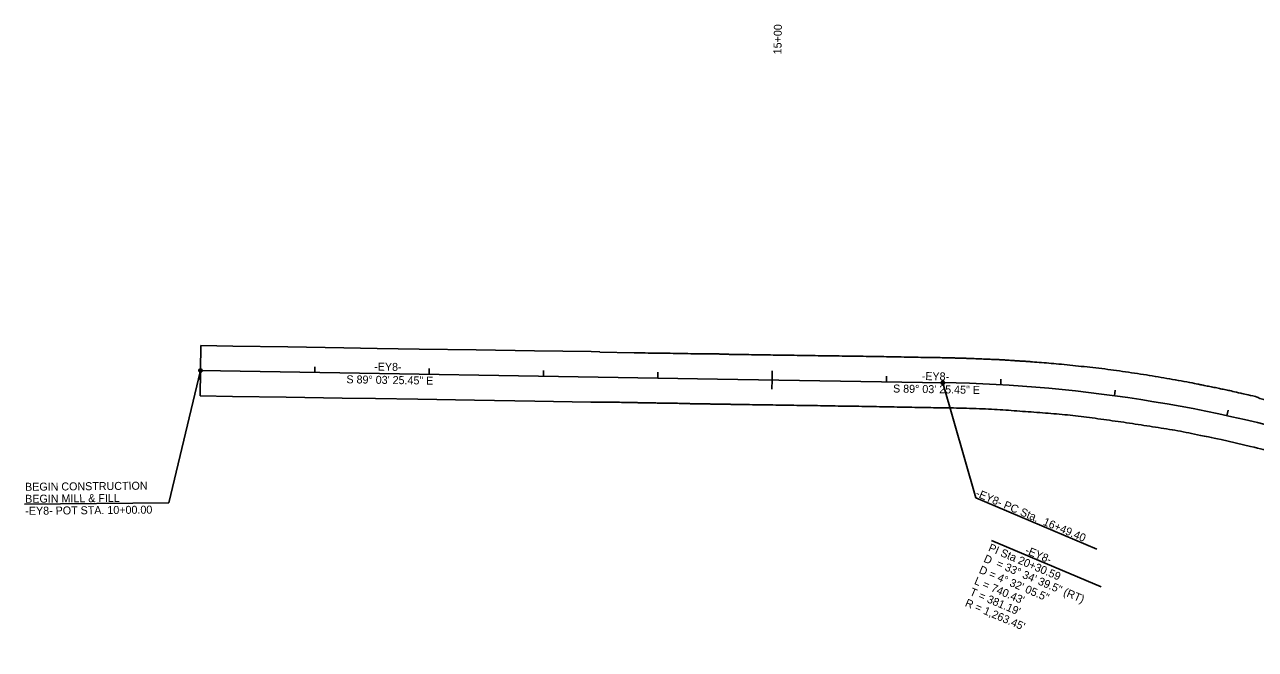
# Model space of a CAD drawing. Extents: x 1616561 to 1622460, y 896726 to 899651.
# Drawn here: x 1616561 to 1617638, y 899105 to 899651 of the extents above; entities that cross this region are included whole.
import ezdxf

# ---------------------------------------------------------------- set-up
doc = ezdxf.new("R2010")
doc.units = 0
for name, color, linetype in [('Prop Dimension Text', 7, 'Continuous'), ('Prop DSN Text', 7, 'Continuous'), ('Prop EOT', 7, 'Continuous'), ('Prop Horizontal Alignment Tick Label', 7, 'Continuous'), ('Prop Shade Light', 7, 'Continuous'), ('Prop Shade Medium', 7, 'Continuous'), ('Prop Terminator CELL', 7, 'Continuous'), ('Sheet North Arrow CELL', 7, 'Continuous'), ('Sheet Title CELL', 7, 'Continuous')]:
    doc.layers.add(name, color=color, linetype=linetype)

msp = doc.modelspace()

# ---------------------------------------------------------------- linework, layer by layer
at = {"layer": 'Prop DSN Text'}
for p, q in [((1617364.6, 899338.1), (1617393.5, 899237.4)), ((1617393.5, 899237.4), (1617499.3, 899192.6))]:
    msp.add_line(p, q, dxfattribs=at)
for centre in [(1616715.3, 899348.7), (1617364.6, 899338.1)]:
    msp.add_circle(centre, 1.5, dxfattribs=at)
at = {"layer": 'Prop Horizontal Alignment Tick Label'}
for p, q in [((1616715.3, 899348.7), (1616715.4, 899356.7)), ((1616715.3, 899348.7), (1616715.1, 899340.7)), ((1617215.2, 899340.5), (1617215.3, 899348.5)), ((1617215.2, 899340.5), (1617215.1, 899332.5))]:
    msp.add_line(p, q, dxfattribs=at)
at = {"layer": 'Prop Shade Light'}
for p, q in [((1616715.6, 899370.5), (1616715.3, 899348.7)), ((1616869.9, 899368.1), (1616840.6, 899368.6)), ((1617064.5, 899364.9), (1617064.6, 899365.2)), ((1617094.5, 899364.2), (1617064.5, 899364.9)), ((1616715.3, 899348.7), (1616714.9, 899326.6)), ((1616715.3, 899348.7), (1617167.6, 899341.3)), ((1617167.6, 899341.3), (1616715.3, 899348.7)), ((1616815.3, 899347.1), (1616815.3, 899352.1)), ((1616915.3, 899345.5), (1616915.3, 899350.5)), ((1617015.2, 899343.8), (1617015.3, 899348.8)), ((1617115.2, 899342.2), (1617115.3, 899347.2)), ((1617315.2, 899338.9), (1617315.3, 899343.9)), ((1617167.6, 899341.3), (1617364.6, 899338.1)), ((1617364.6, 899338.1), (1617167.6, 899341.3)), ((1617415.2, 899336.2), (1617415.4, 899341.2)), ((1617514.7, 899326.6), (1617515.3, 899331.6)), ((1617613.1, 899309.2), (1617614.2, 899314.1)), ((1617608.1, 899288.4), (1617633.7, 899282.4))]:
    msp.add_line(p, q, dxfattribs=at)
for points in [[(1616840.6, 899368.6), (1616791.7, 899369.4), (1616743.5, 899370.1), (1616715.6, 899370.5)], [(1617064.6, 899365.2), (1617057.1, 899365.3), (1617007.4, 899365.9), (1616956.5, 899366.8), (1616906.6, 899367.5), (1616869.9, 899368.1)], [(1616714.9, 899326.6), (1616743.4, 899326.1), (1616790.3, 899325.4), (1616839.1, 899324.6), (1616868.5, 899324.2)], [(1616868.5, 899324.2), (1616905.3, 899323.6), (1616955, 899322.8), (1617007.6, 899322), (1617056.8, 899321.1), (1617064.1, 899321), (1617064.3, 899321.2)]]:
    msp.add_lwpolyline(points, dxfattribs=at)
msp.add_arc((1617343.8, 898074.8), 1263.5, 55.4794, 89.0571, dxfattribs=at)
msp.add_arc((1617343.8, 898074.8), 1263.5, 55.4794, 89.0571, dxfattribs=at)
for points in [[(1617638, 899325.9), (1617631.3, 899327.5), (1617624.6, 899329), (1617617.9, 899330.6), (1617613.3, 899331.7), (1617608.7, 899332.5), (1617604.2, 899333.5), (1617599.3, 899334.5), (1617594.5, 899335.4), (1617589.7, 899336.4), (1617589, 899336.6), (1617588.4, 899336.7), (1617587.8, 899336.8), (1617577.9, 899338.9), (1617568, 899340.5), (1617558.1, 899342.2), (1617547.8, 899344), (1617537.4, 899345.7), (1617527, 899347.2), (1617516.6, 899348.8), (1617506.2, 899350.1), (1617495.7, 899351.3), (1617485.7, 899352.4), (1617475.7, 899353.5), (1617465.7, 899354.4), (1617457.3, 899355.2), (1617448.9, 899355.9), (1617440.6, 899356.5), (1617438.6, 899356.7), (1617436.5, 899356.8), (1617434.5, 899356.9), (1617430.2, 899357.2), (1617425.8, 899357.5), (1617421.5, 899357.7), (1617419.4, 899357.9), (1617417.4, 899358.1), (1617415.4, 899358.2), (1617411.7, 899358.3), (1617408, 899358.5), (1617404.3, 899358.6), (1617398.8, 899358.8), (1617393.4, 899359.1), (1617388, 899359.3), (1617384.7, 899359.4), (1617381.3, 899359.5), (1617378, 899359.6), (1617374.8, 899359.7), (1617371.6, 899359.8), (1617368.4, 899359.9), (1617367.9, 899359.9), (1617367.4, 899359.9), (1617366.8, 899359.9), (1617358.3, 899360.1), (1617349.7, 899360.2), (1617341.1, 899360.3), (1617330.8, 899360.5), (1617320.6, 899360.8), (1617310.3, 899360.9), (1617300, 899361.1), (1617289.6, 899361.2), (1617279.3, 899361.4), (1617268.8, 899361.5), (1617258.3, 899361.7), (1617247.8, 899361.8), (1617237.3, 899362), (1617226.7, 899362.2), (1617216.1, 899362.3), (1617206.7, 899362.4), (1617197.3, 899362.6), (1617187.9, 899362.7), (1617186.8, 899362.7), (1617185.7, 899362.7), (1617184.6, 899362.7), (1617180.9, 899362.8), (1617177.1, 899362.9), (1617173.4, 899363), (1617171.5, 899363), (1617169.7, 899363.2), (1617167.8, 899363.2), (1617164.3, 899363.3), (1617160.8, 899363.2), (1617157.3, 899363.3), (1617146.9, 899363.4), (1617136.4, 899363.6), (1617126, 899363.8), (1617115.5, 899363.9), (1617105, 899364.1), (1617094.5, 899364.2)], [(1617064.3, 899321.2), (1617074.3, 899321), (1617084.2, 899320.9), (1617094.2, 899320.7), (1617098.1, 899320.6), (1617101.9, 899320.6), (1617105.8, 899320.6), (1617109.7, 899320.5), (1617113.7, 899320.3), (1617117.6, 899320.3), (1617120.3, 899320.2), (1617123, 899320.3), (1617125.7, 899320.2), (1617128.4, 899320.2), (1617131.1, 899320.1), (1617133.8, 899320), (1617137.5, 899319.9), (1617141.2, 899319.8), (1617144.9, 899319.7), (1617148.8, 899319.6), (1617152.6, 899319.6), (1617156.5, 899319.6), (1617159.9, 899319.5), (1617163.4, 899319.4), (1617166.8, 899319.3), (1617169.1, 899319.3), (1617171.4, 899319.3), (1617173.7, 899319.3), (1617177.5, 899319.2), (1617181.3, 899319.1), (1617185.1, 899319.1), (1617195.4, 899318.9), (1617205.7, 899318.7), (1617216, 899318.6), (1617226.4, 899318.4), (1617236.8, 899318.3), (1617247.1, 899318.1), (1617257.5, 899318), (1617267.9, 899317.8), (1617278.3, 899317.6), (1617288.6, 899317.5), (1617298.9, 899317.3), (1617309.1, 899317.1), (1617319.5, 899316.9), (1617329.9, 899316.7), (1617340.3, 899316.5), (1617349.5, 899316.3), (1617358.8, 899316.2), (1617368.1, 899316.1), (1617379.5, 899315.9), (1617390.9, 899315.6), (1617402.3, 899315.1), (1617412.2, 899314.7), (1617422, 899313.9), (1617431.9, 899313.2), (1617441.8, 899312.5), (1617451.8, 899311.8), (1617461.7, 899310.9), (1617471.2, 899310.1), (1617480.7, 899309.1), (1617490.2, 899307.9), (1617500.3, 899306.6), (1617510.3, 899305.2), (1617520.3, 899303.8), (1617530.4, 899302.3), (1617540.5, 899300.8), (1617550.6, 899299.2), (1617560.3, 899297.7), (1617570.1, 899296.1), (1617579.8, 899294.1), (1617589.3, 899292.2), (1617598.7, 899290.3), (1617608.1, 899288.4)], [(1617960.3, 899202.8), (1617956.5, 899204.8), (1617952.7, 899206.9), (1617948.9, 899208.9), (1617944.3, 899211.4), (1617939.6, 899213.8), (1617935, 899216.1), (1617926.6, 899220.4), (1617918.1, 899224.7), (1617909.7, 899228.9), (1617905.4, 899231), (1617901.1, 899233.1), (1617896.7, 899235.2), (1617892.6, 899237.1), (1617888.4, 899239.1), (1617884.2, 899241), (1617880.5, 899242.7), (1617876.8, 899244.6), (1617873, 899246.3), (1617868.3, 899248.5), (1617863.4, 899250.5), (1617858.6, 899252.6), (1617850.2, 899256.2), (1617841.8, 899259.8), (1617833.4, 899263.3), (1617824.6, 899266.9), (1617815.8, 899270.4), (1617807, 899273.7), (1617799.1, 899276.6), (1617791.3, 899279.6), (1617783.5, 899282.5), (1617779.2, 899284.1), (1617775, 899285.6), (1617770.7, 899287.2), (1617766.8, 899288.6), (1617762.8, 899289.9), (1617758.8, 899291.2), (1617754.3, 899292.8), (1617749.7, 899294.3), (1617745.1, 899295.8), (1617740.5, 899297.3), (1617735.8, 899298.7), (1617731.2, 899300.2), (1617721, 899303.4), (1617710.8, 899306.5), (1617700.6, 899309.6), (1617691.5, 899312.4), (1617682.4, 899314.8), (1617673.2, 899317), (1617668.2, 899318.1), (1617663.1, 899318.9), (1617658.1, 899320), (1617655.7, 899320.6), (1617653.4, 899321.1), (1617651.1, 899321.7), (1617648.8, 899322.3), (1617646.5, 899322.9), (1617644.2, 899323.6), (1617642.1, 899324.3), (1617640.1, 899325.2), (1617638, 899325.9)], [(1617633.7, 899282.4), (1617643.1, 899280.1), (1617652.5, 899277.7), (1617661.9, 899275.3), (1617671.2, 899272.9), (1617680.4, 899270.4), (1617689.5, 899267.7), (1617698.9, 899265), (1617708.2, 899262.1), (1617717.5, 899259.2), (1617726.8, 899256.3), (1617736, 899253.3), (1617745.2, 899250.3), (1617753.3, 899247.6), (1617761.3, 899244.7), (1617769.2, 899241.7), (1617776.7, 899238.8), (1617784.2, 899235.9), (1617791.7, 899233), (1617800, 899229.7), (1617808.4, 899226.5), (1617816.7, 899223.1), (1617825.1, 899219.7), (1617833.4, 899216), (1617841.8, 899212.2), (1617849.8, 899208.6), (1617857.7, 899205), (1617865.7, 899201.4), (1617873.8, 899197.7), (1617881.9, 899193.9), (1617889.9, 899190.1), (1617898.3, 899186), (1617906.6, 899181.7), (1617914.8, 899177.4), (1617923.4, 899173), (1617931.9, 899168.4), (1617940.3, 899163.7), (1617942.9, 899162.3), (1617945.4, 899160.6), (1617947.8, 899158.9), (1617949.6, 899157.5), (1617951.1, 899156), (1617952.7, 899154.4), (1617953.7, 899153.4), (1617954.6, 899152.3), (1617955.4, 899151.2), (1617957.2, 899148.8), (1617958.7, 899146.3), (1617960.1, 899143.7), (1617960.9, 899142.3), (1617961.5, 899140.9), (1617962.1, 899139.4), (1617962.8, 899137.5), (1617963.3, 899135.7), (1617963.6, 899133.8), (1617963.9, 899131.9), (1617964, 899130), (1617964.1, 899128.1), (1617964.2, 899126.8), (1617964.2, 899125.4), (1617964.2, 899124.1), (1617964.2, 899122.3), (1617964.2, 899120.5), (1617963.9, 899118.8), (1617963.7, 899117.3), (1617963.4, 899115.8), (1617962.9, 899114.4), (1617962.6, 899113.6), (1617962.3, 899112.7), (1617962, 899111.9), (1617961.7, 899111), (1617961.6, 899110.1), (1617961.1, 899109.3), (1617960.4, 899107.8), (1617959.6, 899106.3), (1617958.9, 899104.8)]]:
    msp.add_open_spline(points, degree=3, dxfattribs=at)
at = {"layer": 'Prop Shade Medium'}
msp.add_line((1617407.3, 899200), (1617503.1, 899159.4), dxfattribs=at)
at = {"layer": 'Prop Terminator CELL'}
for p, q in [((1616715.6, 899370.5), (1616714.9, 899326.6)), ((1616714.9, 899326.6), (1616715.6, 899370.5)), ((1616840.6, 899368.6), (1616869.9, 899368.1)), ((1617064.6, 899365.2), (1617064.5, 899364.9)), ((1617064.5, 899364.9), (1617094.5, 899364.2)), ((1616868.5, 899324.2), (1616839.1, 899324.6)), ((1617633.7, 899282.4), (1617608.1, 899288.4))]:
    msp.add_line(p, q, dxfattribs=at)
for points in [[(1616715.6, 899370.5), (1616743.5, 899370.1), (1616791.7, 899369.4), (1616840.6, 899368.6)], [(1616869.9, 899368.1), (1616906.6, 899367.5), (1616956.5, 899366.8), (1617007.4, 899365.9), (1617057.1, 899365.3), (1617064.6, 899365.2)], [(1616839.1, 899324.6), (1616790.3, 899325.4), (1616743.4, 899326.1), (1616714.9, 899326.6)], [(1617064.1, 899321), (1617056.8, 899321.1), (1617007.6, 899322), (1616955, 899322.8), (1616905.3, 899323.6), (1616868.5, 899324.2)]]:
    msp.add_lwpolyline(points, dxfattribs=at)
for points in [[(1617094.5, 899364.2), (1617105, 899364.1), (1617115.5, 899363.9), (1617126, 899363.8), (1617136.4, 899363.6), (1617146.9, 899363.4), (1617157.3, 899363.3), (1617160.8, 899363.2), (1617164.3, 899363.3), (1617167.8, 899363.2), (1617169.7, 899363.2), (1617171.5, 899363), (1617173.4, 899363), (1617177.1, 899362.9), (1617180.9, 899362.8), (1617184.6, 899362.7), (1617185.7, 899362.7), (1617186.8, 899362.7), (1617187.9, 899362.7), (1617197.3, 899362.6), (1617206.7, 899362.4), (1617216.1, 899362.3), (1617226.7, 899362.2), (1617237.3, 899362), (1617247.8, 899361.8), (1617258.3, 899361.7), (1617268.8, 899361.5), (1617279.3, 899361.4), (1617289.6, 899361.2), (1617300, 899361.1), (1617310.3, 899360.9), (1617320.6, 899360.8), (1617330.8, 899360.5), (1617341.1, 899360.3), (1617349.7, 899360.2), (1617358.3, 899360.1), (1617366.8, 899359.9), (1617367.4, 899359.9), (1617367.9, 899359.9), (1617368.4, 899359.9), (1617371.6, 899359.8), (1617374.8, 899359.7), (1617378, 899359.6), (1617381.3, 899359.5), (1617384.7, 899359.4), (1617388, 899359.3), (1617393.4, 899359.1), (1617398.8, 899358.8), (1617404.3, 899358.6), (1617408, 899358.5), (1617411.7, 899358.3), (1617415.4, 899358.2), (1617417.4, 899358.1), (1617419.4, 899357.9), (1617421.5, 899357.7), (1617425.8, 899357.5), (1617430.2, 899357.2), (1617434.5, 899356.9), (1617436.5, 899356.8), (1617438.6, 899356.7), (1617440.6, 899356.5), (1617448.9, 899355.9), (1617457.3, 899355.2), (1617465.7, 899354.4), (1617475.7, 899353.5), (1617485.7, 899352.4), (1617495.7, 899351.3), (1617506.2, 899350.1), (1617516.6, 899348.8), (1617527, 899347.2), (1617537.4, 899345.7), (1617547.8, 899344), (1617558.1, 899342.2), (1617568, 899340.5), (1617577.9, 899338.9), (1617587.8, 899336.8), (1617588.4, 899336.7), (1617589, 899336.6), (1617589.7, 899336.4), (1617594.5, 899335.4), (1617599.3, 899334.5), (1617604.2, 899333.5), (1617608.7, 899332.5), (1617613.3, 899331.7), (1617617.9, 899330.6), (1617624.6, 899329), (1617631.3, 899327.5), (1617638, 899325.9)], [(1617608.1, 899288.4), (1617598.7, 899290.3), (1617589.3, 899292.2), (1617579.8, 899294.1), (1617570.1, 899296.1), (1617560.3, 899297.7), (1617550.6, 899299.2), (1617540.5, 899300.8), (1617530.4, 899302.3), (1617520.3, 899303.8), (1617510.3, 899305.2), (1617500.3, 899306.6), (1617490.2, 899307.9), (1617480.7, 899309.1), (1617471.2, 899310.1), (1617461.7, 899310.9), (1617451.8, 899311.8), (1617441.8, 899312.5), (1617431.9, 899313.2), (1617422, 899313.9), (1617412.2, 899314.7), (1617402.3, 899315.1), (1617390.9, 899315.6), (1617379.5, 899315.9), (1617368.1, 899316.1), (1617358.8, 899316.2), (1617349.5, 899316.3), (1617340.3, 899316.5), (1617329.9, 899316.7), (1617319.5, 899316.9), (1617309.1, 899317.1), (1617298.9, 899317.3), (1617288.6, 899317.5), (1617278.3, 899317.6), (1617267.9, 899317.8), (1617257.5, 899318), (1617247.1, 899318.1), (1617236.8, 899318.3), (1617226.4, 899318.4), (1617216, 899318.6), (1617205.7, 899318.7), (1617195.4, 899318.9), (1617185.1, 899319.1), (1617181.3, 899319.1), (1617177.5, 899319.2), (1617173.7, 899319.3), (1617171.4, 899319.3), (1617169.1, 899319.3), (1617166.8, 899319.3), (1617163.4, 899319.4), (1617159.9, 899319.5), (1617156.5, 899319.6), (1617152.6, 899319.6), (1617148.8, 899319.6), (1617144.9, 899319.7), (1617141.2, 899319.8), (1617137.5, 899319.9), (1617133.8, 899320), (1617131.1, 899320.1), (1617128.4, 899320.2), (1617125.7, 899320.2), (1617123, 899320.3), (1617120.3, 899320.2), (1617117.6, 899320.3), (1617113.7, 899320.3), (1617109.7, 899320.5), (1617105.8, 899320.6), (1617101.9, 899320.6), (1617098.1, 899320.6), (1617094.2, 899320.7), (1617084.2, 899320.9), (1617074.3, 899321), (1617064.3, 899321.2)], [(1617958.9, 899104.8), (1617959.6, 899106.3), (1617960.4, 899107.8), (1617961.1, 899109.3), (1617961.6, 899110.1), (1617961.7, 899111), (1617962, 899111.9), (1617962.3, 899112.7), (1617962.6, 899113.6), (1617962.9, 899114.4), (1617963.4, 899115.8), (1617963.7, 899117.3), (1617963.9, 899118.8), (1617964.2, 899120.5), (1617964.2, 899122.3), (1617964.2, 899124.1), (1617964.2, 899125.4), (1617964.2, 899126.8), (1617964.1, 899128.1), (1617964, 899130), (1617963.9, 899131.9), (1617963.6, 899133.8), (1617963.3, 899135.7), (1617962.8, 899137.5), (1617962.1, 899139.4), (1617961.5, 899140.9), (1617960.9, 899142.3), (1617960.1, 899143.7), (1617958.7, 899146.3), (1617957.2, 899148.8), (1617955.4, 899151.2), (1617954.6, 899152.3), (1617953.7, 899153.4), (1617952.7, 899154.4), (1617951.1, 899156), (1617949.6, 899157.5), (1617947.8, 899158.9), (1617945.4, 899160.6), (1617942.9, 899162.3), (1617940.3, 899163.7), (1617931.9, 899168.4), (1617923.4, 899173), (1617914.8, 899177.4), (1617906.6, 899181.7), (1617898.3, 899186), (1617889.9, 899190.1), (1617881.9, 899193.9), (1617873.8, 899197.7), (1617865.7, 899201.4), (1617857.7, 899205), (1617849.8, 899208.6), (1617841.8, 899212.2), (1617833.4, 899216), (1617825.1, 899219.7), (1617816.7, 899223.1), (1617808.4, 899226.5), (1617800, 899229.7), (1617791.7, 899233), (1617784.2, 899235.9), (1617776.7, 899238.8), (1617769.2, 899241.7), (1617761.3, 899244.7), (1617753.3, 899247.6), (1617745.2, 899250.3), (1617736, 899253.3), (1617726.8, 899256.3), (1617717.5, 899259.2), (1617708.2, 899262.1), (1617698.9, 899265), (1617689.5, 899267.7), (1617680.4, 899270.4), (1617671.2, 899272.9), (1617661.9, 899275.3), (1617652.5, 899277.7), (1617643.1, 899280.1), (1617633.7, 899282.4)]]:
    msp.add_open_spline(points, degree=3, dxfattribs=at)
at = {"layer": 'Sheet North Arrow CELL'}
for p in [(1616715.3, 899348.7), (1616561.5, 899231.7)]:
    msp.add_line(p, (1616687.6, 899232.9), dxfattribs=at)
at = {"layer": 'Sheet Title CELL'}
for q in [(1616715.3, 899348.7), (1617364.6, 899338.1)]:
    msp.add_line((1617167.6, 899341.3), q, dxfattribs=at)
msp.add_arc((1617343.8, 898074.8), 1263.5, 55.4794, 89.0571, dxfattribs=at)
msp.add_arc((1617343.8, 898074.8), 1263.5, 55.4794, 89.0571, dxfattribs=at)

# ---------------------------------------------------------------- texts
at = {"layer": 'Prop Dimension Text'}
for s, p in [('-EY8-', (1616867.2, 899348.7)), ('S 89%%d 03\' 25.45" E', (1616842.9, 899337.6)), ('-EY8-', (1617346.1, 899340.4)), ('S 89%%d 03\' 25.45" E', (1617321, 899329.5))]:
    msp.add_text(s, height=7, rotation=359.0571, dxfattribs=at).set_placement(p)
at = {"layer": 'Prop DSN Text'}
msp.add_text('-EY8- PC Sta.  16+49.40', height=7, rotation=337.0441, dxfattribs=at).set_placement((1617392.7, 899238.9))
at = {"layer": 'Prop EOT'}
msp.add_text('15+00', height=7, rotation=89.0571, dxfattribs=at).set_placement((1617223.4, 899625.3))
at = {"layer": 'Prop Shade Medium'}
for s, p in [('PI Sta 20+30.59', (1617403.8, 899191.2)), ('-EY8-', (1617435.9, 899189)), ('D', (1617399.7, 899181.6)), ('= 33%%d 34\' 39.5" (RT)', (1617410.7, 899177.3)), ('D = 4%%d 32\' 05.5"', (1617395.6, 899171.9)), ("T = 381.19'", (1617387.5, 899152.6)), ("L = 740.43'", (1617391.5, 899162.2)), ("R = 1,263.45'", (1617383.4, 899142.9))]:
    msp.add_text(s, height=7, rotation=337.0441, dxfattribs=at).set_placement(p)
at = {"layer": 'Sheet North Arrow CELL'}
for s, p in [('BEGIN CONSTRUCTION', (1616561.9, 899243.5)), ('BEGIN MILL & FILL', (1616562, 899233)), ('-EY8- POT STA. 10+00.00', (1616562.1, 899222.5))]:
    msp.add_text(s, height=7, rotation=0.5575, dxfattribs=at).set_placement(p)

doc.saveas('drawing.dxf')
